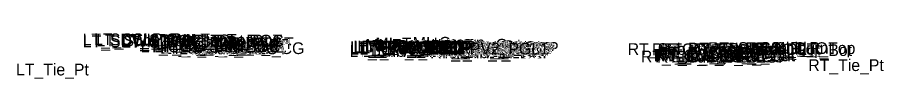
# Model space of a CAD drawing. Extents: x -26 to 4229, y -10 to 9523.
# Drawn here: x 1072.2 to 1219, y 512 to 519.8 of the extents above; entities that cross this region are included whole.
import ezdxf

# ---------------------------------------------------------------- set-up
doc = ezdxf.new("R2010")
doc.units = 0
doc.layers.add('Default', color=7, linetype='Continuous')

msp = doc.modelspace()

# ---------------------------------------------------------------- texts
at = {"layer": 'Default'}
for s, p in [('LT_SDWK_Out_Top', (1083.24, 517.75)), ('LT_CSLP_Pnt', (1085.17, 517.78)), ('LT_Sub_Trench_Out_DLT', (1085.55, 517.58)), ('LT_SDWK_In_Top', (1089.86, 517.65)), ('LT_SDWK_Out_Bot', (1083.27, 517.42)), ('LT_SDWK_In_Bot', (1089.89, 517.32)), ('LT_CG1_Shelf_Out', (1093.05, 516.55)), ('LT_CG_Top_Face', (1094.76, 517.54)), ('LT_CG_Top_BOC', (1095.28, 517.54)), ('LT_CG_Bot_BOC', (1095.31, 516.54)), ('LT_CG_Top_Gut', (1095.74, 517.04)), ('LT_Sub_OEOP', (1096.36, 516.3)), ('LT_Sub_OEOT_CG', (1096.87, 516.25)), ('LT_CG_Bot_IE', (1099.41, 516.5)), ('LT_Sub_OEOT', (1099.58, 516.21)), ('LT_PV2_OEOT', (1099.67, 516.84)), ('LT_PV3_OEOT', (1099.67, 516.59)), ('LT_PV1_OEOT', (1100.24, 517.09)), ('LT_PV2_OEEOP', (1128.56, 516.4)), ('LT_PV3_OEEOP', (1128.56, 516.15)), ('LT_PV1_OEEOP', (1129.12, 516.52)), ('LT_PV2_IEEOP', (1129.2, 516.4)), ('LT_PV1_IEEOP', (1129.77, 516.52)), ('LT_PV2_PGL1', (1130.13, 516.4)), ('LT_PV3_PGL1', (1130.13, 516.15)), ('LT_PV2_PGL', (1130.46, 516.4)), ('LT_PV1_PGL', (1131.03, 516.65)), ('MI_Face In', (1131.15, 516.81)), ('MI_Bot In', (1132.13, 516.65)), ('MI_Top In', (1132.86, 517.06)), ('MI_Crown', (1139.17, 517.18)), ('RT_PV2_OEEOP', (1142.21, 516.18)), ('RT_PV1_OEEOP', (1142.78, 516.3)), ('RT_PV2_IEEOP', (1142.86, 516.18)), ('MI_Face Out', (1143.21, 516.59)), ('MI_Top Out', (1143.42, 516.84)), ('RT_PV1_IEEOP', (1143.43, 516.3)), ('RT_PV2_PGL1', (1143.79, 516.18)), ('RT_PV2_PGL', (1144.12, 516.18)), ('MI_Bot Out', (1144.21, 516.43)), ('RT_PV1_PGL', (1144.69, 516.43)), ('RT_Sub_Trench_Out_DLT', (1175.59, 516.1)), ('RT_SDWK_In_Top', (1185.81, 516.17)), ('RT_SDWK_Out_Top', (1189.19, 516.27)), ('RT_Shld_O', (1195.54, 516.26)), ('CSLP_Pnt', (1197.87, 516.3)), ('LT_Sub_OEEOP', (1128.46, 515.77)), ('LT_PV4_PGL', (1130.46, 515.77)), ('RT_Sub_OEEOP', (1142.12, 515.55)), ('RT_PV3_OEEOP', (1142.21, 515.93)), ('RT_PV3_PGL1', (1143.79, 515.93)), ('RT_PV4_PGL', (1144.12, 515.55)), ('RT_Sub_OEOT_CG', (1177.82, 514.84)), ('RT_CG_Top_Face', (1179.71, 516.06)), ('RT_CG1_Shelf_Out', (1180, 515.03)), ('RT_CG_Bot_IE', (1180.37, 515.09)), ('RT_Sub_OEOT', (1180.53, 514.8)), ('RT_PV2_OEOT', (1180.63, 515.43)), ('RT_PV3_OEOT', (1180.63, 515.18)), ('RT_CG_Top_Gut', (1180.69, 515.56)), ('RT_PV1_OEOT', (1181.19, 515.68)), ('RT_CG_Top_BOC', (1181.24, 516.06)), ('RT_CG_Bot_BOC', (1181.27, 515.04)), ('RT_Sub_OEOP', (1183.82, 514.78)), ('RT_SDWK_In_Bot', (1185.84, 515.83)), ('RT_SDWK_Out_Bot', (1189.22, 515.93)), ('RT_Tie_Pt', (1206.19, 513.36)), ('LT_Tie_Pt', (1071.95, 512.61))]:
    msp.add_text(s, height=2, dxfattribs=at).set_placement(p)

doc.saveas('drawing.dxf')
